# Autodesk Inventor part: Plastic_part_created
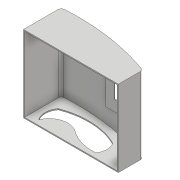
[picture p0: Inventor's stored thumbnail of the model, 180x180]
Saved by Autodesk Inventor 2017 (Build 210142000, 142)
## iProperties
Created: 2016-09
Part Number: Plastic_part_created
Material: Generic
Document SubType Name: Modeling
Designer: Gaurav
Density: 1 g/cm^3
Appearance: Default
Author: Gaurav
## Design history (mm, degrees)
sketch "Sketch5"
  geometry: L1 (129.407, 7.97)-(129.407, -51.345); L2 (129.407, -51.345)-(-129.407, -51.345); L3 (-129.407, -51.345)-(-129.407, 41.969); L4 (-129.407, 51.345)-(129.407, -51.345); L5 (129.407, 51.345)-(-129.407, -51.345); A1 r 622.494 centre (-84.638, -569.537) between (122.739, 17.399) and (-119.975, 51.953); A2 r 10 centre (-119.407, 41.969) between (-119.975, 51.953) and (-129.407, 41.969); A3 r 10 centre (119.407, 7.97) between (129.407, 7.97) and (122.739, 17.399); 2 further points
  constraints: 10 end point, 8 point on circle, 4 tangent, 3 centre point, 3 point on line, 2 midpoint, 1 equal radius, 1 parallel
  dimensions: "d9" = 10 radius of A2 (derived)
extrude "Extrusion2" new body sketch "Sketch5" distance "d10" = 209.25; taper "d11" = 0 deg
shell "Shell2" dims "d12" = 3
workplane "Work Plane5"
sketch "Sketch7"
  geometry: L1 (-15, 58)-(-95, 58); L2 (-95, 58)-(-95, 136); L3 (-95, 136)-(-15, 136); L4 (-15, 136)-(-15, 58); L5 (-15, 58)-(-95, 136); L6 (-95, 58)-(-15, 136); 2 further points
  constraints: 12 end point, 2 midpoint, 2 parallel, 1 horizontal, 1 perpendicular
feature "Rest1" sketch "Sketch7" dims "d14" = 10, "d15" = 0, "d16" = 0, "d17" = 0, "d18" = 5 deg, "d19" = -5 deg, "d20" = 2
sketch "Sketch9"
  geometry: L1 (22, -11)-(42, -11); L2 (42, -11)-(42, -53); L3 (42, -53)-(22, -53); L4 (22, -53)-(22, -11); L5 (22, -11)-(42, -53); L6 (42, -11)-(22, -53); 2 further points
  constraints: 12 end point, 2 midpoint, 2 parallel, 1 horizontal, 1 perpendicular
extrude "Extrusion3" cut sketch "Sketch9" distance "d59" = 10; taper "d60" = 0 deg
sketch "Sketch11"
  geometry: A1 r 194.225 centre (30.972, -166.162) between (101, 15) and (-55, 8); A2 r 41.049 centre (-21, -15) between (-55, 8) and (-55, -38); A3 r 43.503 centre (66.514, -11.518) between (101.013, -38.018) and (101, 15); A4 r 115.242 centre (-44.693, 76.78) between (-55, -38) and (23.995, -15.755); A5 r 50.387 centre (54.027, -56.213) between (101.013, -38.018) and (23.995, -15.755); 1 further point
  constraints: 10 point on circle, 5 centre point, 1 tangent
extrude "Extrusion4" cut sketch "Sketch11" distance "d76" = 10; taper "d77" = 0 deg
body "Solid2"
other parameters: "d13" = 33.5
